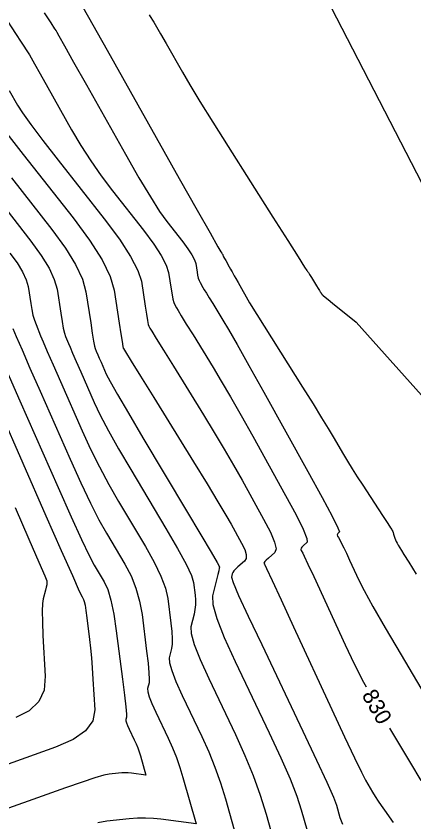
# Model space of a CAD drawing. Extents: x 1715724 to 1716561, y 394063 to 395906.
# Drawn here: x 1716035.8 to 1716070.7, y 394975.2 to 395046 of the extents above; entities that cross this region are included whole.
import ezdxf

# ---------------------------------------------------------------- set-up
doc = ezdxf.new("R2010")
doc.units = 0
for name, color, linetype in [('DT_X_Contour_Major', 7, 'Continuous'), ('DT_X_Contour_Minor', 7, 'Continuous'), ('GE_P_CL_10', 7, 'Continuous')]:
    doc.layers.add(name, color=color, linetype=linetype)

msp = doc.modelspace()

# ---------------------------------------------------------------- linework, layer by layer
at = {"layer": 'DT_X_Contour_Major'}
for points in [[(1716033.841, 395047.347), (1716036.153, 395043.821), (1716036.94, 395042.616), (1716037.381, 395041.832), (1716037.874, 395040.958), (1716038.558, 395039.743), (1716040.639, 395036.047), (1716041.449, 395034.672), (1716042.319, 395033.318), (1716043.248, 395031.986), (1716044.236, 395030.675), (1716046.95, 395027.208), (1716047.852, 395026.002), (1716048.519, 395024.982), (1716048.954, 395024.15), (1716049.155, 395023.506), (1716049.381, 395022.036), (1716049.463, 395021.539), (1716049.54, 395021.152), (1716049.611, 395020.873), (1716049.678, 395020.704), (1716049.849, 395020.397), (1716049.988, 395020.162), (1716050.278, 395019.687), (1716050.717, 395018.972), (1716051.306, 395018.017), (1716053.077, 395015.149), (1716053.793, 395013.965), (1716054.613, 395012.563), (1716055.536, 395010.944), (1716056.563, 395009.107), (1716059.441, 395003.918), (1716060.369, 395002.201), (1716060.993, 395000.942), (1716061.313, 395000.14), (1716061.331, 394999.796), (1716060.972, 394999.488), (1716060.861, 394999.376), (1716060.796, 394999.271), (1716060.777, 394999.173), (1716060.804, 394999.081), (1716060.939, 394998.847), (1716061.08, 394998.559), (1716061.404, 394997.871), (1716061.91, 394996.782), (1716064.676, 394990.788), (1716065.469, 394989.122), (1716066.29, 394987.501), (1716066.503, 394987.106)], [(1716035.212, 395025.209), (1716035.852, 395024.335), (1716036.335, 395023.551), (1716036.658, 395022.859), (1716036.823, 395022.258), (1716037.05, 395020.775), (1716037.143, 395020.242), (1716037.253, 395019.755), (1716037.38, 395019.314), (1716037.522, 395018.918), (1716037.925, 395017.925), (1716038.147, 395017.395), (1716038.51, 395016.553), (1716039.014, 395015.397), (1716039.66, 395013.927), (1716041.57, 395009.59), (1716042.307, 395007.983), (1716043.086, 395006.412), (1716043.906, 395004.878), (1716044.768, 395003.38), (1716047.12, 394999.437), (1716047.905, 394998.042), (1716048.495, 394996.813), (1716048.89, 394995.751), (1716049.089, 394994.856), (1716049.363, 394992.692), (1716049.443, 394991.944), (1716049.479, 394991.322), (1716049.471, 394990.827), (1716049.419, 394990.459), (1716049.221, 394989.647), (1716049.237, 394989.212), (1716049.432, 394988.516), (1716049.806, 394987.558), (1716050.36, 394986.339), (1716052.075, 394982.742), (1716052.687, 394981.387), (1716053.237, 394980.021), (1716053.724, 394978.644), (1716054.148, 394977.256), (1716055.983, 394970.751)], [(1716068.574, 394983.452), (1716070.392, 394980.377), (1716071.31, 394978.863)]]:
    msp.add_lwpolyline(points, dxfattribs=at)
at = {"layer": 'DT_X_Contour_Minor'}
for points in [[(1716041.62, 395046.826), (1716043.762, 395043.023), (1716050.104, 395031.761), (1716051.674, 395028.975), (1716052.806, 395026.972), (1716053.5, 395025.752), (1716053.754, 395025.315), (1716053.849, 395025.194), (1716053.88, 395025.152), (1716053.904, 395025.116), (1716053.919, 395025.087), (1716053.926, 395025.065), (1716053.934, 395025.014), (1716053.951, 395024.97), (1716053.997, 395024.879), (1716054.072, 395024.739), (1716054.176, 395024.551), (1716054.493, 395023.985), (1716054.598, 395023.796), (1716054.678, 395023.654), (1716054.732, 395023.559), (1716054.76, 395023.511), (1716054.801, 395023.444), (1716054.841, 395023.375), (1716054.931, 395023.215), (1716055.07, 395022.965), (1716055.259, 395022.625), (1716056.254, 395020.83), (1716060.929, 395013.412), (1716061.848, 395011.949), (1716062.602, 395010.737), (1716063.189, 395009.777), (1716063.611, 395009.069), (1716064.515, 395007.516), (1716064.875, 395006.91), (1716065.278, 395006.256), (1716065.722, 395005.553), (1716066.209, 395004.803), (1716067.562, 395002.738), (1716068.011, 395002.053), (1716068.343, 395001.546), (1716068.558, 395001.218), (1716068.656, 395001.067), (1716068.761, 395000.904), (1716068.801, 395000.834), (1716068.841, 395000.746), (1716068.881, 395000.639), (1716068.922, 395000.515), (1716069.031, 395000.159), (1716069.08, 395000.02), (1716069.146, 394999.872), (1716069.227, 394999.712), (1716069.324, 394999.543), (1716069.605, 394999.078), (1716069.819, 394998.729), (1716070.253, 394998.033), (1716070.904, 394996.989)], [(1716038.245, 395046.308), (1716038.807, 395045.451), (1716039.151, 395044.922), (1716039.28, 395044.721), (1716039.334, 395044.625), (1716039.512, 395044.309), (1716040.007, 395043.43), (1716040.818, 395041.991), (1716041.945, 395039.989), (1716045.372, 395033.904), (1716046.562, 395031.823), (1716047.562, 395030.145), (1716048.374, 395028.869), (1716048.995, 395027.995), (1716050.4, 395026.201), (1716050.866, 395025.577), (1716051.211, 395025.049), (1716051.436, 395024.619), (1716051.54, 395024.285), (1716051.657, 395023.525), (1716051.707, 395023.255), (1716051.768, 395023.015), (1716051.842, 395022.806), (1716051.927, 395022.627), (1716052.171, 395022.191), (1716052.293, 395021.979), (1716052.478, 395021.671), (1716052.724, 395021.265), (1716053.033, 395020.764), (1716053.939, 395019.297), (1716054.417, 395018.489), (1716055.173, 395017.166), (1716056.205, 395015.328), (1716057.514, 395012.975), (1716061.376, 395006.013), (1716062.636, 395003.723), (1716063.52, 395002.074), (1716064.03, 395001.066), (1716064.163, 395000.699), (1716064.02, 395000.575), (1716063.982, 395000.517), (1716063.978, 395000.436), (1716064.007, 395000.333), (1716064.07, 395000.206), (1716064.28, 394999.839), (1716064.388, 394999.635), (1716064.552, 394999.3), (1716064.773, 394998.833), (1716065.051, 394998.235), (1716065.868, 394996.464), (1716066.33, 394995.555), (1716067.102, 394994.157), (1716068.185, 394992.27), (1716069.579, 394989.894), (1716073.711, 394982.906)], [(1716047.444, 395046.137), (1716047.542, 395046.001), (1716047.611, 395045.902), (1716047.757, 395045.685), (1716047.872, 395045.496), (1716048.108, 395045.09), (1716048.465, 395044.469), (1716048.942, 395043.631), (1716050.375, 395041.109), (1716051.03, 395039.991), (1716051.919, 395038.527), (1716053.042, 395036.718), (1716054.399, 395034.564), (1716058.33, 395028.358), (1716059.622, 395026.321), (1716060.547, 395024.862), (1716061.107, 395023.981), (1716061.301, 395023.679), (1716061.331, 395023.646), (1716061.363, 395023.6), (1716061.435, 395023.488), (1716061.546, 395023.311), (1716061.699, 395023.067), (1716062.158, 395022.33), (1716062.309, 395022.086), (1716062.419, 395021.91), (1716062.487, 395021.801), (1716062.513, 395021.758), (1716062.528, 395021.733), (1716062.533, 395021.724), (1716062.537, 395021.717), (1716062.541, 395021.71), (1716062.545, 395021.704), (1716062.554, 395021.691), (1716062.558, 395021.684), (1716062.565, 395021.673), (1716062.574, 395021.659), (1716062.585, 395021.64), (1716062.64, 395021.546), (1716062.669, 395021.526), (1716062.729, 395021.478), (1716062.899, 395021.341), (1716063.177, 395021.117), (1716063.565, 395020.805), (1716065.628, 395019.144), (1716072.36, 395011.596)], [(1716035.172, 395039.496), (1716035.907, 395038.19), (1716036.337, 395037.521), (1716037.075, 395036.492), (1716038.122, 395035.103), (1716039.477, 395033.356), (1716043.501, 395028.215), (1716044.837, 395026.427), (1716045.827, 395024.915), (1716046.472, 395023.682), (1716046.77, 395022.726), (1716047.104, 395020.547), (1716047.218, 395019.824), (1716047.311, 395019.288), (1716047.381, 395018.94), (1716047.429, 395018.78), (1716047.528, 395018.603), (1716047.684, 395018.345), (1716048.077, 395017.704), (1716048.709, 395016.679), (1716049.579, 395015.27), (1716052.215, 395011.002), (1716053.169, 395009.441), (1716054.053, 395007.961), (1716054.867, 395006.56), (1716055.613, 395005.239), (1716057.507, 395001.824), (1716058.101, 395000.68), (1716058.465, 394999.81), (1716058.597, 394999.215), (1716058.498, 394998.893), (1716057.925, 394998.401), (1716057.74, 394998.235), (1716057.614, 394998.106), (1716057.547, 394998.013), (1716057.539, 394997.957), (1716057.597, 394997.856), (1716057.772, 394997.483), (1716058.255, 394996.442), (1716059.046, 394994.731), (1716060.145, 394992.351), (1716063.484, 394985.112), (1716064.609, 394982.688), (1716065.478, 394980.844), (1716066.093, 394979.58), (1716066.453, 394978.897), (1716067.074, 394977.848), (1716067.313, 394977.452), (1716067.566, 394977.054), (1716067.834, 394976.651), (1716068.115, 394976.245), (1716068.882, 394975.158)], [(1716034.968, 395035.716), (1716036.405, 395033.88), (1716040.775, 395028.299), (1716042.23, 395026.332), (1716043.316, 395024.617), (1716044.035, 395023.156), (1716044.385, 395021.946), (1716044.828, 395019.058), (1716044.974, 395018.108), (1716045.082, 395017.425), (1716045.15, 395017.007), (1716045.18, 395016.857), (1716045.206, 395016.81), (1716045.379, 395016.529), (1716045.877, 395015.72), (1716046.701, 395014.385), (1716047.852, 395012.523), (1716051.353, 395006.854), (1716052.544, 395004.917), (1716053.493, 395003.358), (1716054.199, 395002.176), (1716054.662, 395001.371), (1716055.572, 394999.729), (1716055.844, 394999.167), (1716055.975, 394998.712), (1716055.967, 394998.364), (1716055.819, 394998.123), (1716055.236, 394997.622), (1716055.042, 394997.444), (1716054.895, 394997.285), (1716054.796, 394997.145), (1716054.745, 394997.023), (1716054.673, 394996.725), (1716054.819, 394996.27), (1716055.311, 394995.132), (1716056.15, 394993.309), (1716057.336, 394990.801), (1716060.96, 394983.201), (1716062.163, 394980.658), (1716063.055, 394978.725), (1716063.636, 394977.405), (1716063.905, 394976.696), (1716064.208, 394975.621), (1716064.433, 394975.024)], [(1716035.367, 395031.807), (1716038.921, 395027.269), (1716040.106, 395025.651), (1716040.998, 395024.202), (1716041.597, 395022.92), (1716041.901, 395021.808), (1716042.322, 395019.065), (1716042.464, 395018.154), (1716042.577, 395017.477), (1716042.659, 395017.035), (1716042.71, 395016.828), (1716042.808, 395016.587), (1716042.949, 395016.255), (1716043.071, 395015.976), (1716043.227, 395015.62), (1716043.69, 395014.571), (1716044.021, 395013.926), (1716044.667, 395012.778), (1716045.629, 395011.127), (1716046.907, 395008.972), (1716050.735, 395002.555), (1716051.992, 395000.446), (1716052.89, 394998.932), (1716053.431, 394998.011), (1716053.614, 394997.685), (1716053.623, 394997.608), (1716053.61, 394997.516), (1716053.564, 394997.299), (1716053.485, 394996.956), (1716053.028, 394995.074), (1716053.055, 394994.316), (1716053.394, 394993.103), (1716054.046, 394991.436), (1716055.01, 394989.314), (1716057.998, 394983.048), (1716059.015, 394980.864), (1716059.824, 394979.011), (1716060.425, 394977.488), (1716060.818, 394976.296), (1716061.59, 394973.559)], [(1716034.329, 395029.735), (1716037.066, 395026.239), (1716037.979, 395024.993), (1716038.666, 395023.877), (1716039.127, 395022.89), (1716039.362, 395022.033), (1716039.686, 395019.92), (1716039.804, 395019.198), (1716039.915, 395018.616), (1716040.019, 395018.174), (1716040.116, 395017.873), (1716040.366, 395017.256), (1716040.504, 395016.927), (1716040.729, 395016.404), (1716041.043, 395015.686), (1716041.444, 395014.774), (1716042.63, 395012.081), (1716043.164, 395010.955), (1716043.877, 395009.595), (1716044.768, 395008.002), (1716045.837, 395006.176), (1716048.928, 395000.996), (1716049.948, 394999.244), (1716050.693, 394997.872), (1716051.16, 394996.881), (1716051.352, 394996.271), (1716051.493, 394995.15), (1716051.527, 394994.73), (1716051.522, 394994.31), (1716051.478, 394993.892), (1716051.396, 394993.474), (1716051.125, 394992.36), (1716051.146, 394991.764), (1716051.413, 394990.809), (1716051.926, 394989.497), (1716052.685, 394987.827), (1716055.037, 394982.895), (1716055.866, 394981.071), (1716056.592, 394979.296), (1716057.214, 394977.571), (1716057.731, 394975.897), (1716058.972, 394971.497)], [(1716035.483, 395018.593), (1716035.789, 395017.864), (1716036.29, 395016.701), (1716036.985, 395015.107), (1716037.876, 395013.08), (1716040.511, 395007.1), (1716041.451, 395005.011), (1716042.296, 395003.228), (1716043.045, 395001.753), (1716043.698, 395000.585), (1716045.313, 394997.878), (1716045.862, 394996.839), (1716046.297, 394995.754), (1716046.619, 394994.621), (1716046.827, 394993.442), (1716047.232, 394990.234), (1716047.359, 394989.157), (1716047.436, 394988.334), (1716047.464, 394987.763), (1716047.442, 394987.445), (1716047.318, 394986.934), (1716047.328, 394986.66), (1716047.45, 394986.222), (1716047.686, 394985.619), (1716048.034, 394984.852), (1716049.114, 394982.589), (1716049.499, 394981.736), (1716049.845, 394980.877), (1716050.151, 394980.01), (1716050.418, 394979.136), (1716051.573, 394975.043), (1716048.495, 394975.458), (1716047.826, 394975.526), (1716047.137, 394975.552), (1716046.429, 394975.538), (1716045.701, 394975.481), (1716043.733, 394975.276), (1716042.937, 394975.155)], [(1716034.957, 395014.818), (1716036.092, 395012.234), (1716039.451, 395004.61), (1716040.594, 395002.039), (1716041.505, 395000.045), (1716042.183, 394998.629), (1716042.628, 394997.789), (1716043.505, 394996.318), (1716043.818, 394995.637), (1716044.099, 394994.694), (1716044.348, 394993.491), (1716044.565, 394992.027), (1716045.102, 394987.776), (1716045.275, 394986.371), (1716045.394, 394985.345), (1716045.457, 394984.698), (1716045.466, 394984.43), (1716045.415, 394984.22), (1716045.419, 394984.108), (1716045.469, 394983.928), (1716045.566, 394983.68), (1716045.709, 394983.365), (1716046.152, 394982.435), (1716046.31, 394982.085), (1716046.452, 394981.732), (1716046.578, 394981.376), (1716046.688, 394981.017), (1716047.162, 394979.336), (1716045.898, 394979.506), (1716045.623, 394979.534), (1716045.34, 394979.545), (1716045.049, 394979.539), (1716044.75, 394979.516), (1716043.942, 394979.431), (1716043.476, 394979.332), (1716042.683, 394979.098), (1716041.564, 394978.729), (1716040.119, 394978.225), (1716032.613, 394975.557)], [(1716034.308, 395011.387), (1716038.391, 395002.119), (1716039.738, 394999.067), (1716040.714, 394996.862), (1716041.321, 394995.504), (1716041.558, 394994.993), (1716041.698, 394994.759), (1716041.755, 394994.593), (1716041.821, 394994.269), (1716041.898, 394993.788), (1716041.983, 394993.15), (1716042.225, 394991.237), (1716042.311, 394990.483), (1716042.389, 394989.654), (1716042.458, 394988.751), (1716042.519, 394987.773), (1716042.671, 394985.066), (1716042.499, 394984.099), (1716041.87, 394983.228), (1716040.784, 394982.454), (1716039.241, 394981.776), (1716030.973, 394978.838)], [(1716035.677, 395002.85), (1716036.889, 395000.062), (1716037.756, 394998.057), (1716038.28, 394996.834), (1716038.46, 394996.394), (1716038.482, 394996.265), (1716038.48, 394996.186), (1716038.456, 394996.049), (1716038.411, 394995.851), (1716038.344, 394995.595), (1716038.138, 394994.831), (1716038.079, 394994.414), (1716038.059, 394993.735), (1716038.076, 394992.794), (1716038.132, 394991.592), (1716038.331, 394988.036), (1716038.225, 394986.808), (1716037.757, 394985.792), (1716036.927, 394984.987), (1716035.736, 394984.394)]]:
    msp.add_lwpolyline(points, dxfattribs=at)
at = {"layer": 'GE_P_CL_10'}
msp.add_line((1716249.46, 394685.42), (1715852.538, 395456.564), dxfattribs=at)

# ---------------------------------------------------------------- texts
at = {"layer": 'DT_X_Contour_Major'}
msp.add_text('830', height=1.4, rotation=299.54515, dxfattribs=at).set_placement((1716066.087, 394986.37))

doc.saveas('drawing.dxf')
